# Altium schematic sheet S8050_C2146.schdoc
size 127 x 101 mm
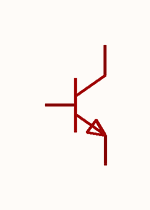
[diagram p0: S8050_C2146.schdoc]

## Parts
Q?  s8050 j3y(range:200-350)  [SOT-23-3_L3.0-W1.7-P0.95-LS2.9-BR]  (value not drawn)

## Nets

Not connected (* = marked no-connect by the designer): Q? 1(B) 2(E) 3(C)

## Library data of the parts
Q? = s8050 j3y(range:200-350): 晶体管类型:NPN;集电极电流(Ic):500mA;集射极击穿电压(Vceo):25V;耗散功率(Pd):300mW;直流电流增益(hFE):200;; Manufacturer: CJ(江苏长电/长晶); Symbol: S8050_C2146; AddInBom: yes; ModelId: 89cb27a44ab2466697082bb9fd73a7d0; ModelName: SOT-23-3L_L2.9-W1.6-H1.1-LS2.8-P0.95; ModelTransform: 114.173,110.236,0,90,0,0,0,0,0; type: NPN; Current - Collector(Ic): 500mA; Collector - Emitter Voltage VCEO: 25V; Pd - Power Dissipation: 300mW; DC Current Gain: 200; Transition frequency(fT): 150MHz; Current - Collector Cutoff: 100nA; Vce Saturation(VCE(sat)): 600mV; Emitter-Base Voltage(Vebo): 5V; Number: 1个NPN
